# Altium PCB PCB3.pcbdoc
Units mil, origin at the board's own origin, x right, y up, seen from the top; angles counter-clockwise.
Board outline 4373.7 x 2860 mil, 2 copper layers (Top Layer, Bottom Layer), stack 2.757 mil thick; 6 components, 37 nets, 70 pads, 2 vias.
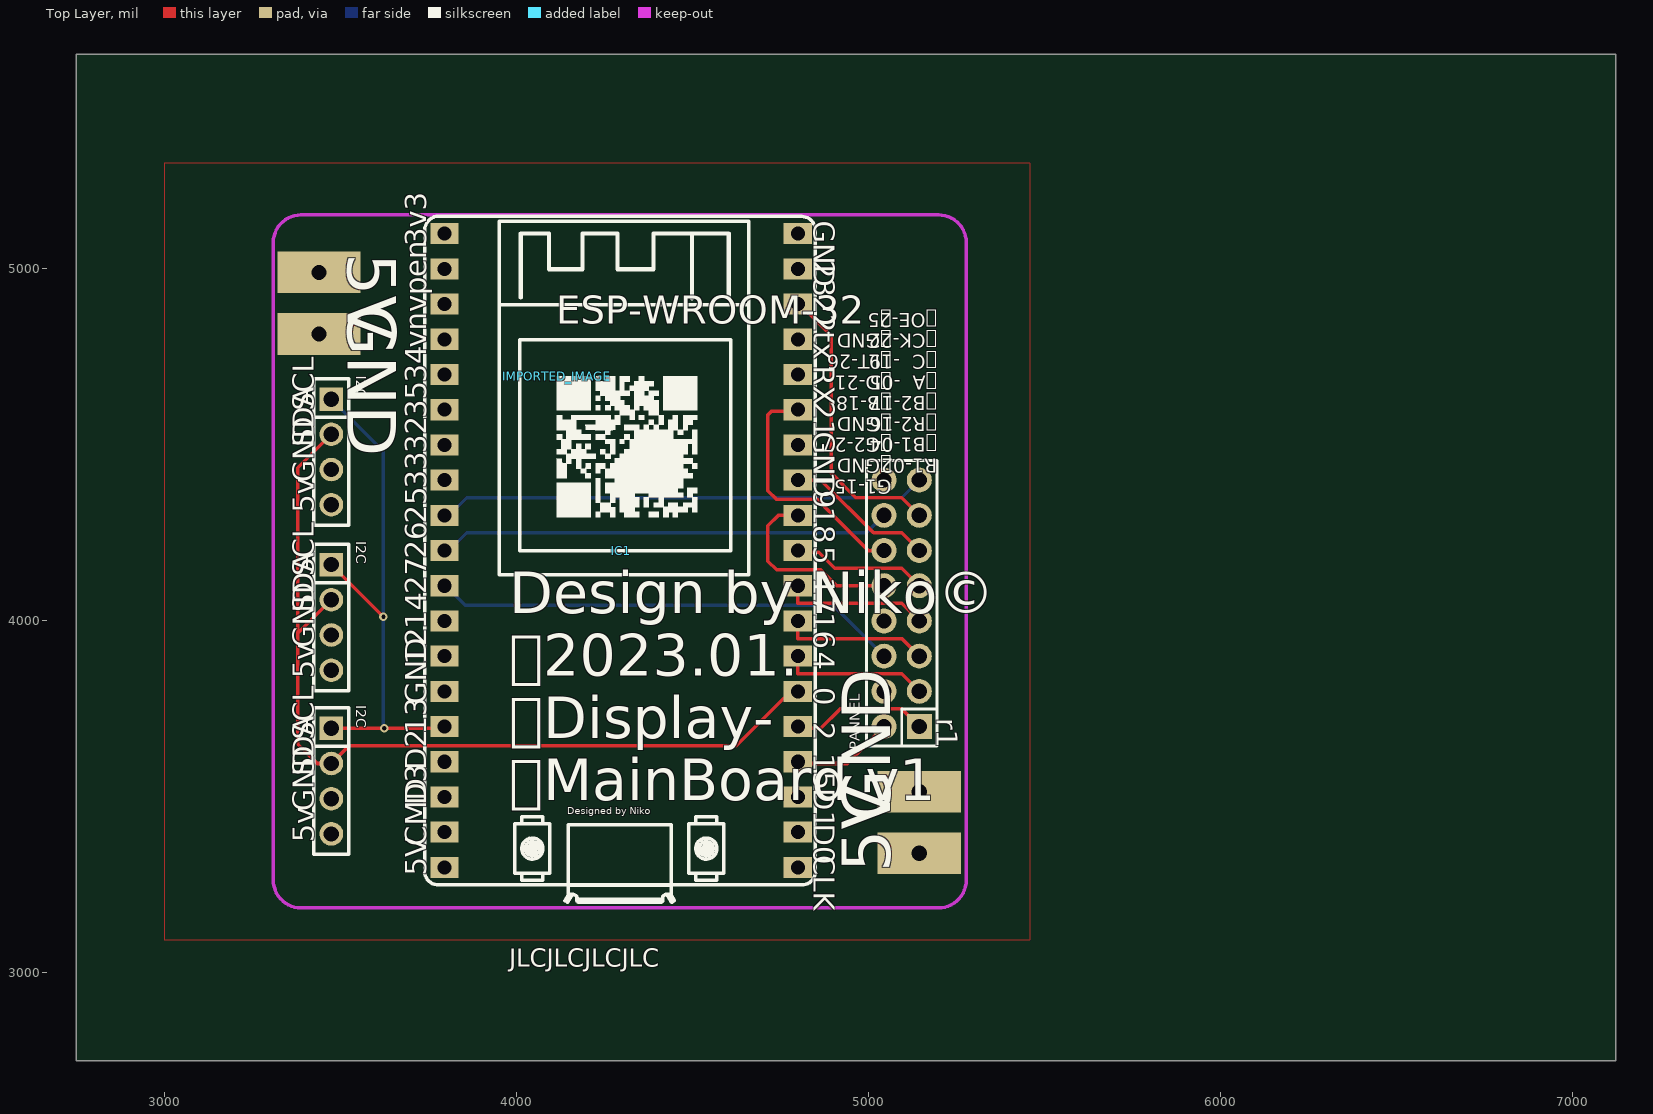
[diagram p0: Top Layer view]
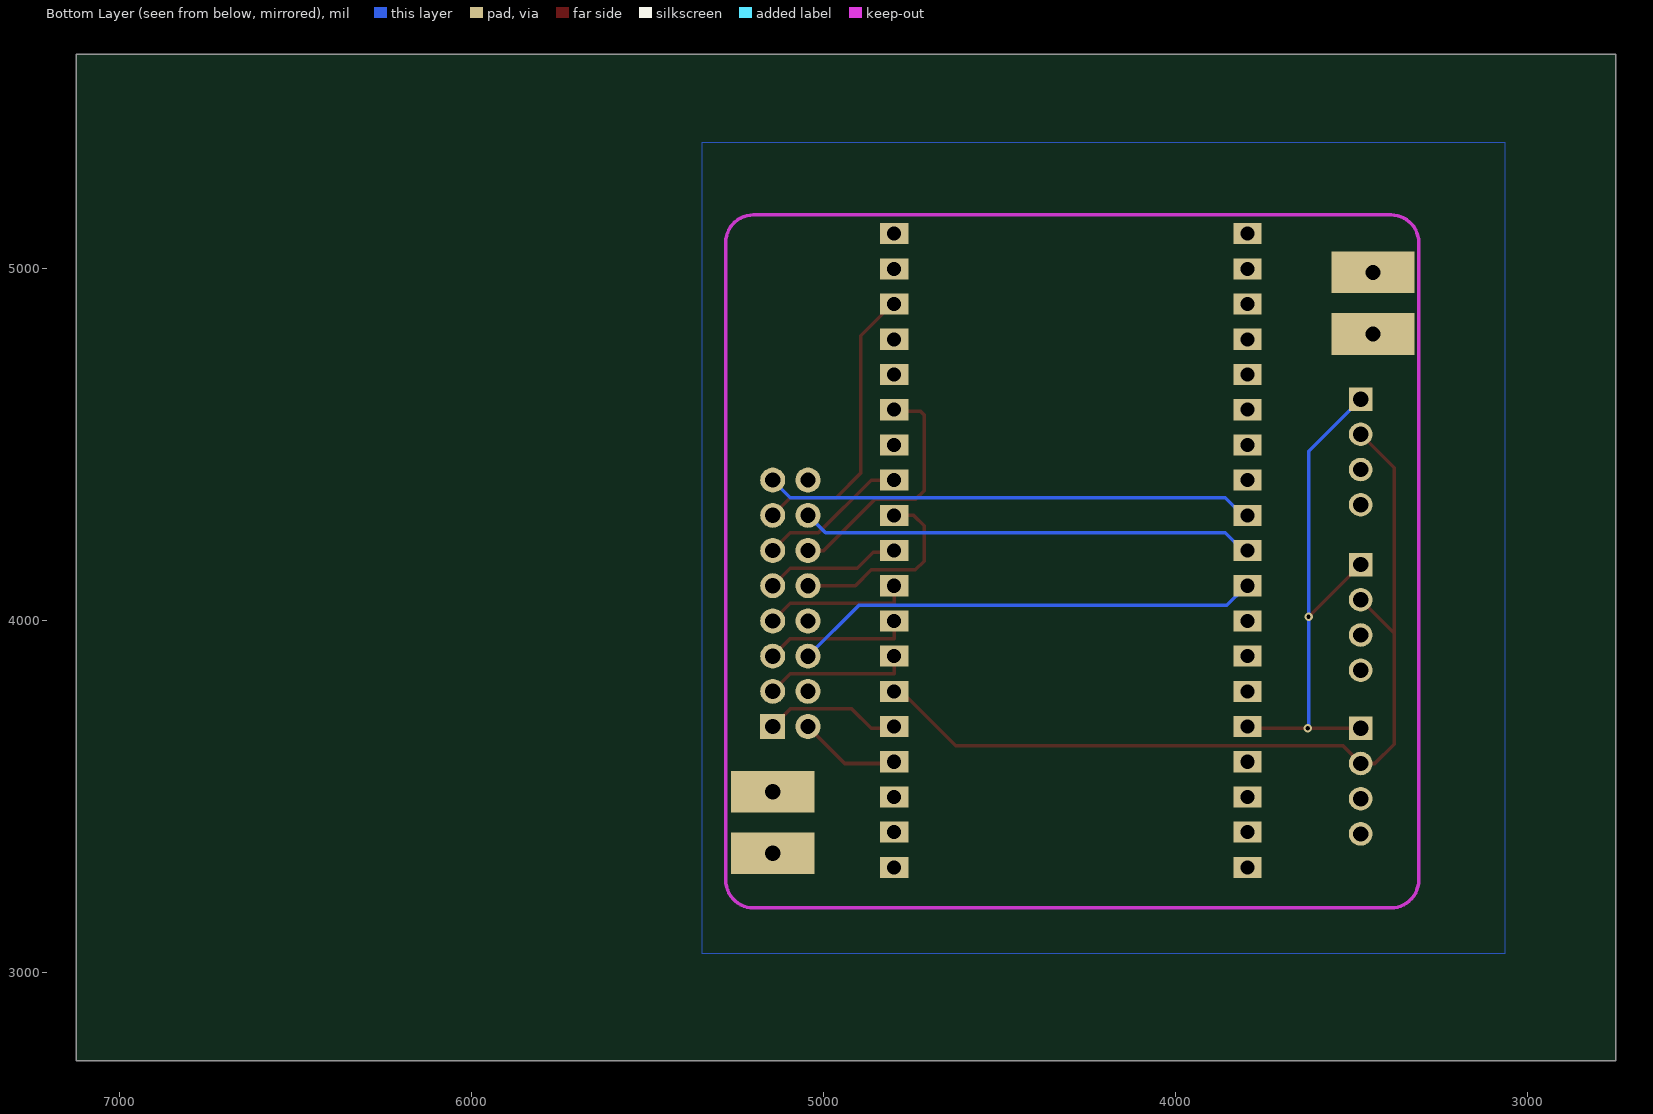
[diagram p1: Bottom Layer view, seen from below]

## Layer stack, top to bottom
Top Layer: signal copper 1.379
Bottom Layer: signal copper 1.378

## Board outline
7123.7,2750 2750,2750 2750,5610 7123.7,5610

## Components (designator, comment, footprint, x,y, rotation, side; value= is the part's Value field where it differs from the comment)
I2C "HDR-F_2.54_1x4P" HDR-TH_4P-P2.54-V-F 3475,3545 r270 top
I2C "HDR-F_2.54_1x4P" HDR-TH_4P-P2.54-V-F 3475,4010 r270 top
I2C "HDR-F_2.54_1x4P" HDR-TH_4P-P2.54-V-F 3475,4480 r270 top
IC1 "ESP32-DevKitC" COMM-TH_NODEMCU-32SLUA 4350,4200 r0 top
IMPORTED_IMAGE "IMPORTED_IMAGE" IMPORTED_IMAGE 4115,4695 r0 top
PANNEL "HDR-F-2.54_2x8" HDR-TH_16P-P2.54-V-F-R2-C8-S2.54-1 5095,4050 r90 top

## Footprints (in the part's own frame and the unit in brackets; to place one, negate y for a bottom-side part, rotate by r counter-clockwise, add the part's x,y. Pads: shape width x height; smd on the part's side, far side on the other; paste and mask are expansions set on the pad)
COMM-TH_NODEMCU-32SLUA [mil]
  rect 80x60 hole 40: 1(-553.43,900) 2(-553.43,800) 3(-553.43,700) 4(-553.43,600) 5(-553.43,500) 6(-553.43,400) 7(-553.43,300) 8(-553.43,200) 9(-553.43,100) 10(-553.43,0) 11(-553.43,-100) 12(-553.43,-200) 13(-553.43,-300) 14(-553.43,-400) 15(-553.43,-500) 16(-553.43,-600) 17(-553.43,-700) 18(-553.43,-800) 19(-553.43,-900) 20(450,-900) 21(450,-800) 22(450,-700) 23(450,-600) 24(450,-500) 25(450,-400) 26(450,-300) 27(450,-200) 28(450,-100) 29(450,0) 30(450,100) 31(450,200) 32(450,300) 33(450,400) 34(450,500) 35(450,600) 36(450,700) 37(450,800) 38(450,900)
  silkscreen extent -610,-999 500,950
HDR-TH_4P-P2.54-V-F [mm]
  rect 1.7x1.7 hole 1.1: 1(-3.81,0)
  round 1.7 hole 1.1: 2(-1.27,0) 3(1.27,0) 4(3.81,0)
  silkscreen extent -5.29,-1.27 5.29,1.27
HDR-TH_16P-P2.54-V-F-R2-C8-S2.54-1 [mm]
  rect 1.8x1.8 hole 1.1: 1(-8.89,-1.27)
  round 1.8 hole 1.1: 2(-8.89,1.27) 3(-6.35,-1.27) 4(-6.35,1.27) 5(-3.81,-1.27) 6(-3.81,1.27) 7(-1.27,-1.27) 8(-1.27,1.27) 9(1.27,-1.27) 10(1.27,1.27) 11(3.81,-1.27) 12(3.81,1.27) 13(6.35,-1.27) 14(6.35,1.27) 15(8.89,-1.27) 16(8.89,1.27)
  silkscreen extent -10.3,-2.54 10.3,2.54
IMPORTED_IMAGE [mil]
  silkscreen extent 0,-400 400,0

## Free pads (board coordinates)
  rect 236.22x118.11 hole 43.31: 1(3440,4815) 1(3440,4990) 1(5145,3340) 1(5145,3515)

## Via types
v1: diameter 24.02, hole 12.01, Top Layer to Bottom Layer, 2 vias

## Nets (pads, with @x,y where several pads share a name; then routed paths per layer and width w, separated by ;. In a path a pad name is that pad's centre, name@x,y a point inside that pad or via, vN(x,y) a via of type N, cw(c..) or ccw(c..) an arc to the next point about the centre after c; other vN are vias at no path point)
3.3V: IC1.1
5V: I2C.4 IC1.19 pad.1@3440,4990 pad.1@5145,3340
EN: IC1.2
GND: I2C.3 IC1.14 IC1.32 IC1.38 pad.1@3440,4815 pad.1@5145,3515 PANNEL.4 PANNEL.8 PANNEL.16
IO0: I2C.2 IC1.25 | length 2586.4
  Top Layer w10: I2C.2@3475,4060 3380,3965 ; I2C.2@3475,4530 3380,4435 3380,3965 ; IC1.25@4805,3800 4780,3800 4625,3645 3525,3645 3475,3595 3435,3595 3380,3650 3380,3965
IO1: IC1.35
IO2: IC1.24 PANNEL.1 | length 385.6
  Top Layer w10: IC1.24@4805,3700 4810,3695 4865,3695 4920,3750 5095,3750 PANNEL.1
IO3: IC1.34
IO4: IC1.26 PANNEL.3 | length 420.7
  Top Layer w10: IC1.26@4805,3900 IC1.26 4800,3850 5095,3850 PANNEL.3
IO5: IC1.29 PANNEL.9 | length 386.4
  Top Layer w10: IC1.29 4804.94,4195.06 4859.94,4195.06 4905,4150 5095,4150 PANNEL.9
IO6: IC1.20
IO7: IC1.21
IO9: IC1.16
IO10: IC1.17
IO11: IC1.18
IO12: IC1.13
IO13: I2C.1 IC1.15 | length 1534.9
  Top Layer w10: I2C.1@3475,3695 v1(3625,3695) 3796.57,3695 IC1.15@3801.57,3700 ; I2C.1@3475,4160 v1(3622.89,4012.11)
  Bottom Layer w10: I2C.1@3475,4630 3622.89,4482.11 v1(3622.89,4012.11) 3622.89,3697.11 v1(3625,3695)
IO14: IC1.12
IO15: IC1.23 PANNEL.2 | length 285.6
  Top Layer w10: IC1.23@4805,3600 4810,3595 4940,3595 PANNEL.2
IO16: IC1.27 PANNEL.5 | length 420.7
  Top Layer w10: IC1.27@4805,4000 IC1.27 4800,3950 5095,3950 PANNEL.5
IO17: IC1.28 PANNEL.7 | length 412.3
  Top Layer w10: IC1.28@4796.19,4091.19 4791.57,4086.57 4800,4078.14 4800,4050 5095,4050 PANNEL.7
IO18: IC1.30 PANNEL.10 | length 533.8
  Top Layer w10: IC1.30@4777.37,4300 4745,4300 4715,4270 4715,4170 4740,4145 4865,4145 4910,4100 PANNEL.10
IO19: IC1.31 PANNEL.11 | length 422.8
  Top Layer w10: IC1.31@4805,4400 4865,4400 5015,4250 5095,4250 PANNEL.11
IO21: IC1.33 PANNEL.12 | length 710.2
  Top Layer w10: IC1.33@4804,4599 4800,4595 4725,4595 4715,4585 4715,4370 4740,4345 4855,4345 5000,4200 PANNEL.12
IO22: IC1.36 PANNEL.13 | length 809.9
  Top Layer w10: IC1.36@4810,4895 4895,4810 4895,4420 4965,4350 5095,4350 PANNEL.13
IO23: IC1.37
IO25: IC1.9 PANNEL.15 | length 1383.5
  Bottom Layer w10: IC1.9@3805,4295 3860,4350 5095,4350 PANNEL.15
IO26: IC1.10 PANNEL.14 | length 1283.5
  Bottom Layer w10: IC1.10@3805,4195 3860,4250 4995,4250 PANNEL.14
IO27: IC1.11 PANNEL.6 | length 1320.8
  Bottom Layer w10: IC1.11@3805,4095 3855,4045 4900,4045 PANNEL.6
IO32: IC1.7
IO33: IC1.8
IO34: IC1.5
IO35: IC1.6
IO36: IC1.3
IO39: IC1.4
NET8: IC1.22
"": 

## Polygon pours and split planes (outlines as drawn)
5V on Top Layer (solid, pour order 0): 3000,3095 5460,3095 5460,5300 3000,5300
GND on Bottom Layer (solid, pour order 1): 3065,3055 5345,3055 5345,5360 3065,5360

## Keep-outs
Keep-Out Layer:
  lines w10 net "": 3310,3263.74 ccw(c3388.74,3263.74) 3388.74,3185 5199.76,3185 ccw(c5199.76,3263.74) 5278.5,3263.74 5278.5,5074.76 ccw(c5199.76,5074.76) 5199.76,5153.5 3388.74,5153.5 ccw(c3388.74,5074.76) 3310,5074.76 3310,3263.74

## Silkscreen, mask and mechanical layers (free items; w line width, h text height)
Top Silkscreen Layer:
  text "5V" at 3521.75,5044.07 h137.8 r270
  text "GND" at 3521.75,4899.35 h137.8 r270
  text "G1-15 /  GND /  G2-27 /  GND /  B-18 /  D-21 /  LT-26 /  GND /  " at 5066.75,4874.15 h39.37 r180
  text "R1-02   /  B1-04   /  R2-16  /  B2-17   /  A  -05   /  C  -19   /  CK-22   /  OE-25" at 5196.75,4874.15 h39.37 r180
  text "SCL" at 3425,4597.52 h59.06 r90
  text "SDA" at 3425,4495.19 h59.06 r90
  text "GND" at 3425,4393.85 h59.06 r90
  text "5v" at 3425,4306.83 h59.06 r90
  text "SCL" at 3425,4127.52 h59.06 r90
  text "SDA" at 3425,4025.19 h59.06 r90
  text "GND" at 3425,3923.85 h59.06 r90
  text "5v" at 3425,3836.83 h59.06 r90
  text "r1" at 5195,3723.17 h59.06 r270
  text "SCL" at 3425,3662.52 h59.06 r90
  text "SDA" at 3425,3560.19 h59.06 r90
  text "Design by Niko©  /  2023.01.  /  Display-  /  MainBoard v1" at 3980,3490 h118.11
  text "GND" at 3425,3458.85 h59.06 r90
  text "GND" at 5063.25,3430.65 h137.8 r90
  text "5v" at 3425,3371.83 h59.06 r90
  text "5V" at 5063.25,3285.93 h137.8 r90
  text "JLCJLCJLCJLC" at 3980.44,3017.48 h51.1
